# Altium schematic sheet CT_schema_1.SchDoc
size 645 x 603 mm
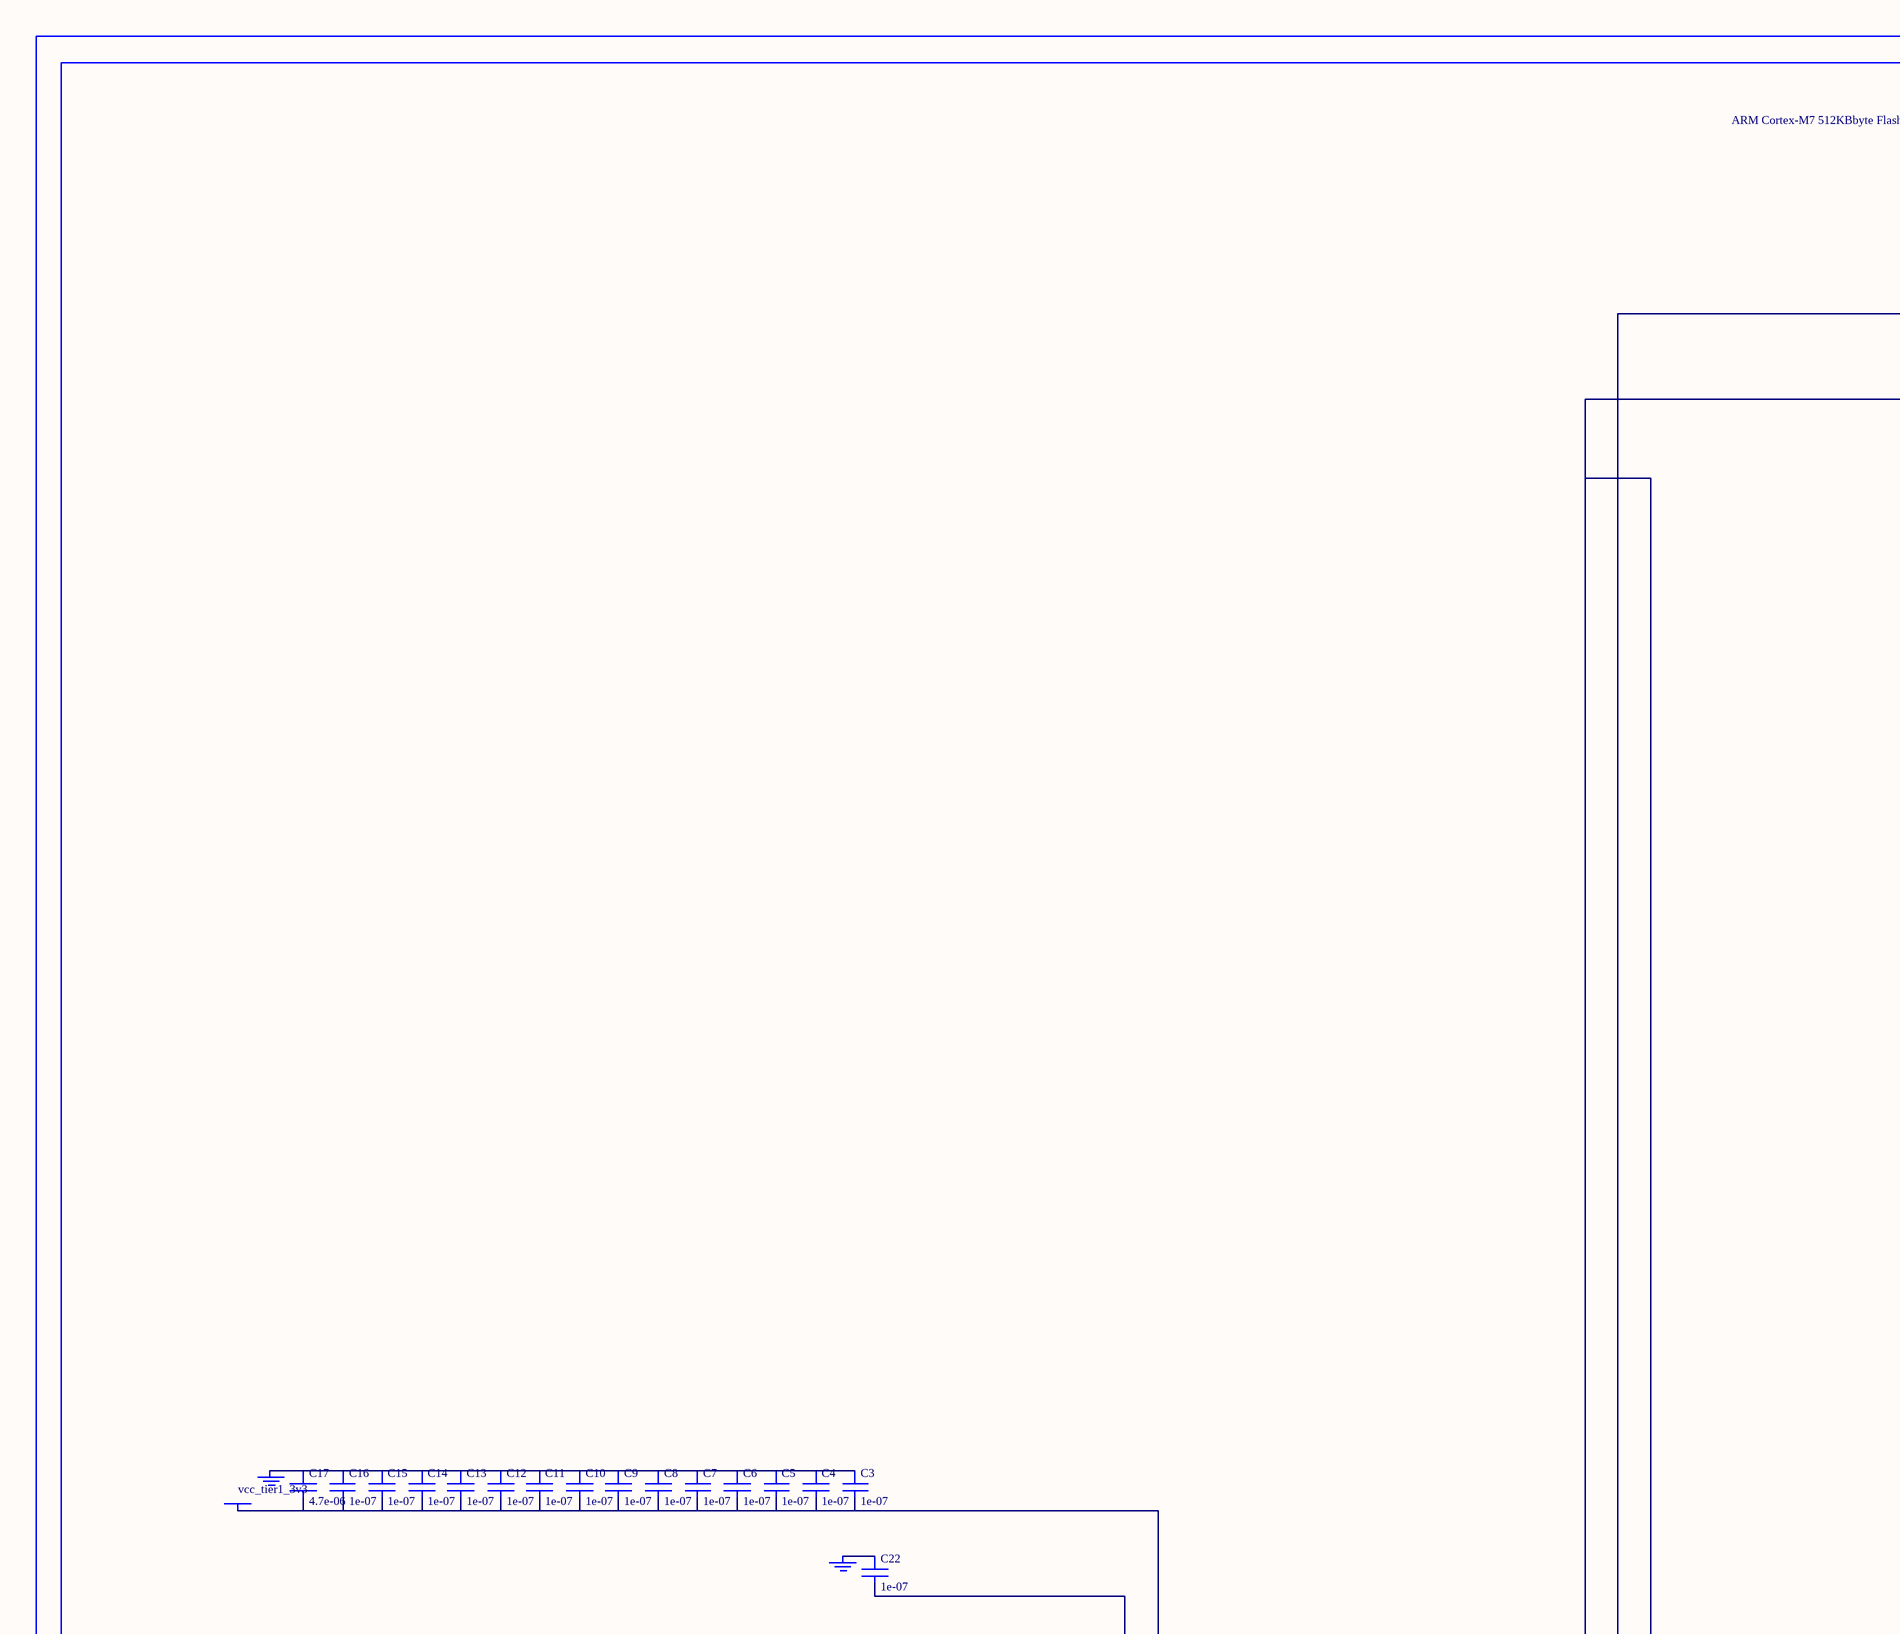
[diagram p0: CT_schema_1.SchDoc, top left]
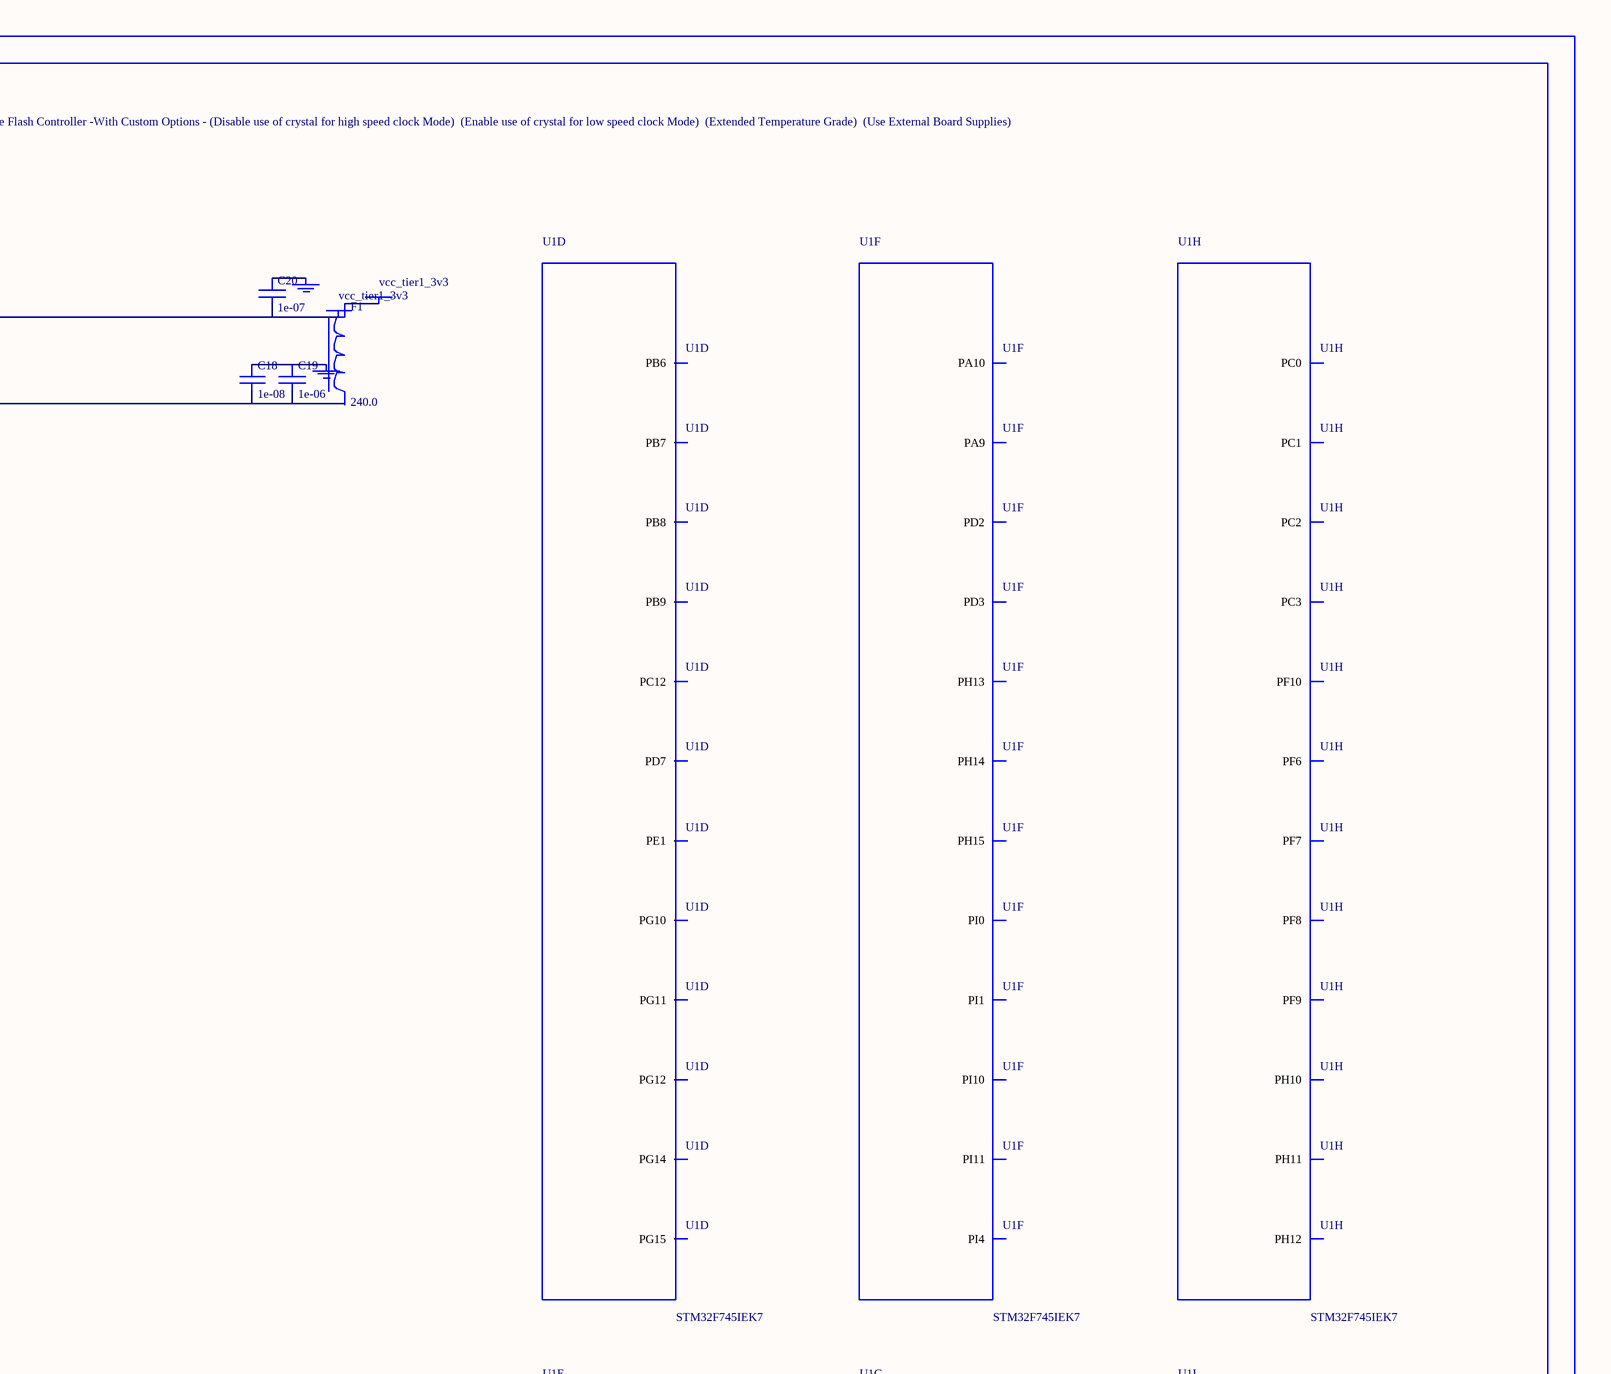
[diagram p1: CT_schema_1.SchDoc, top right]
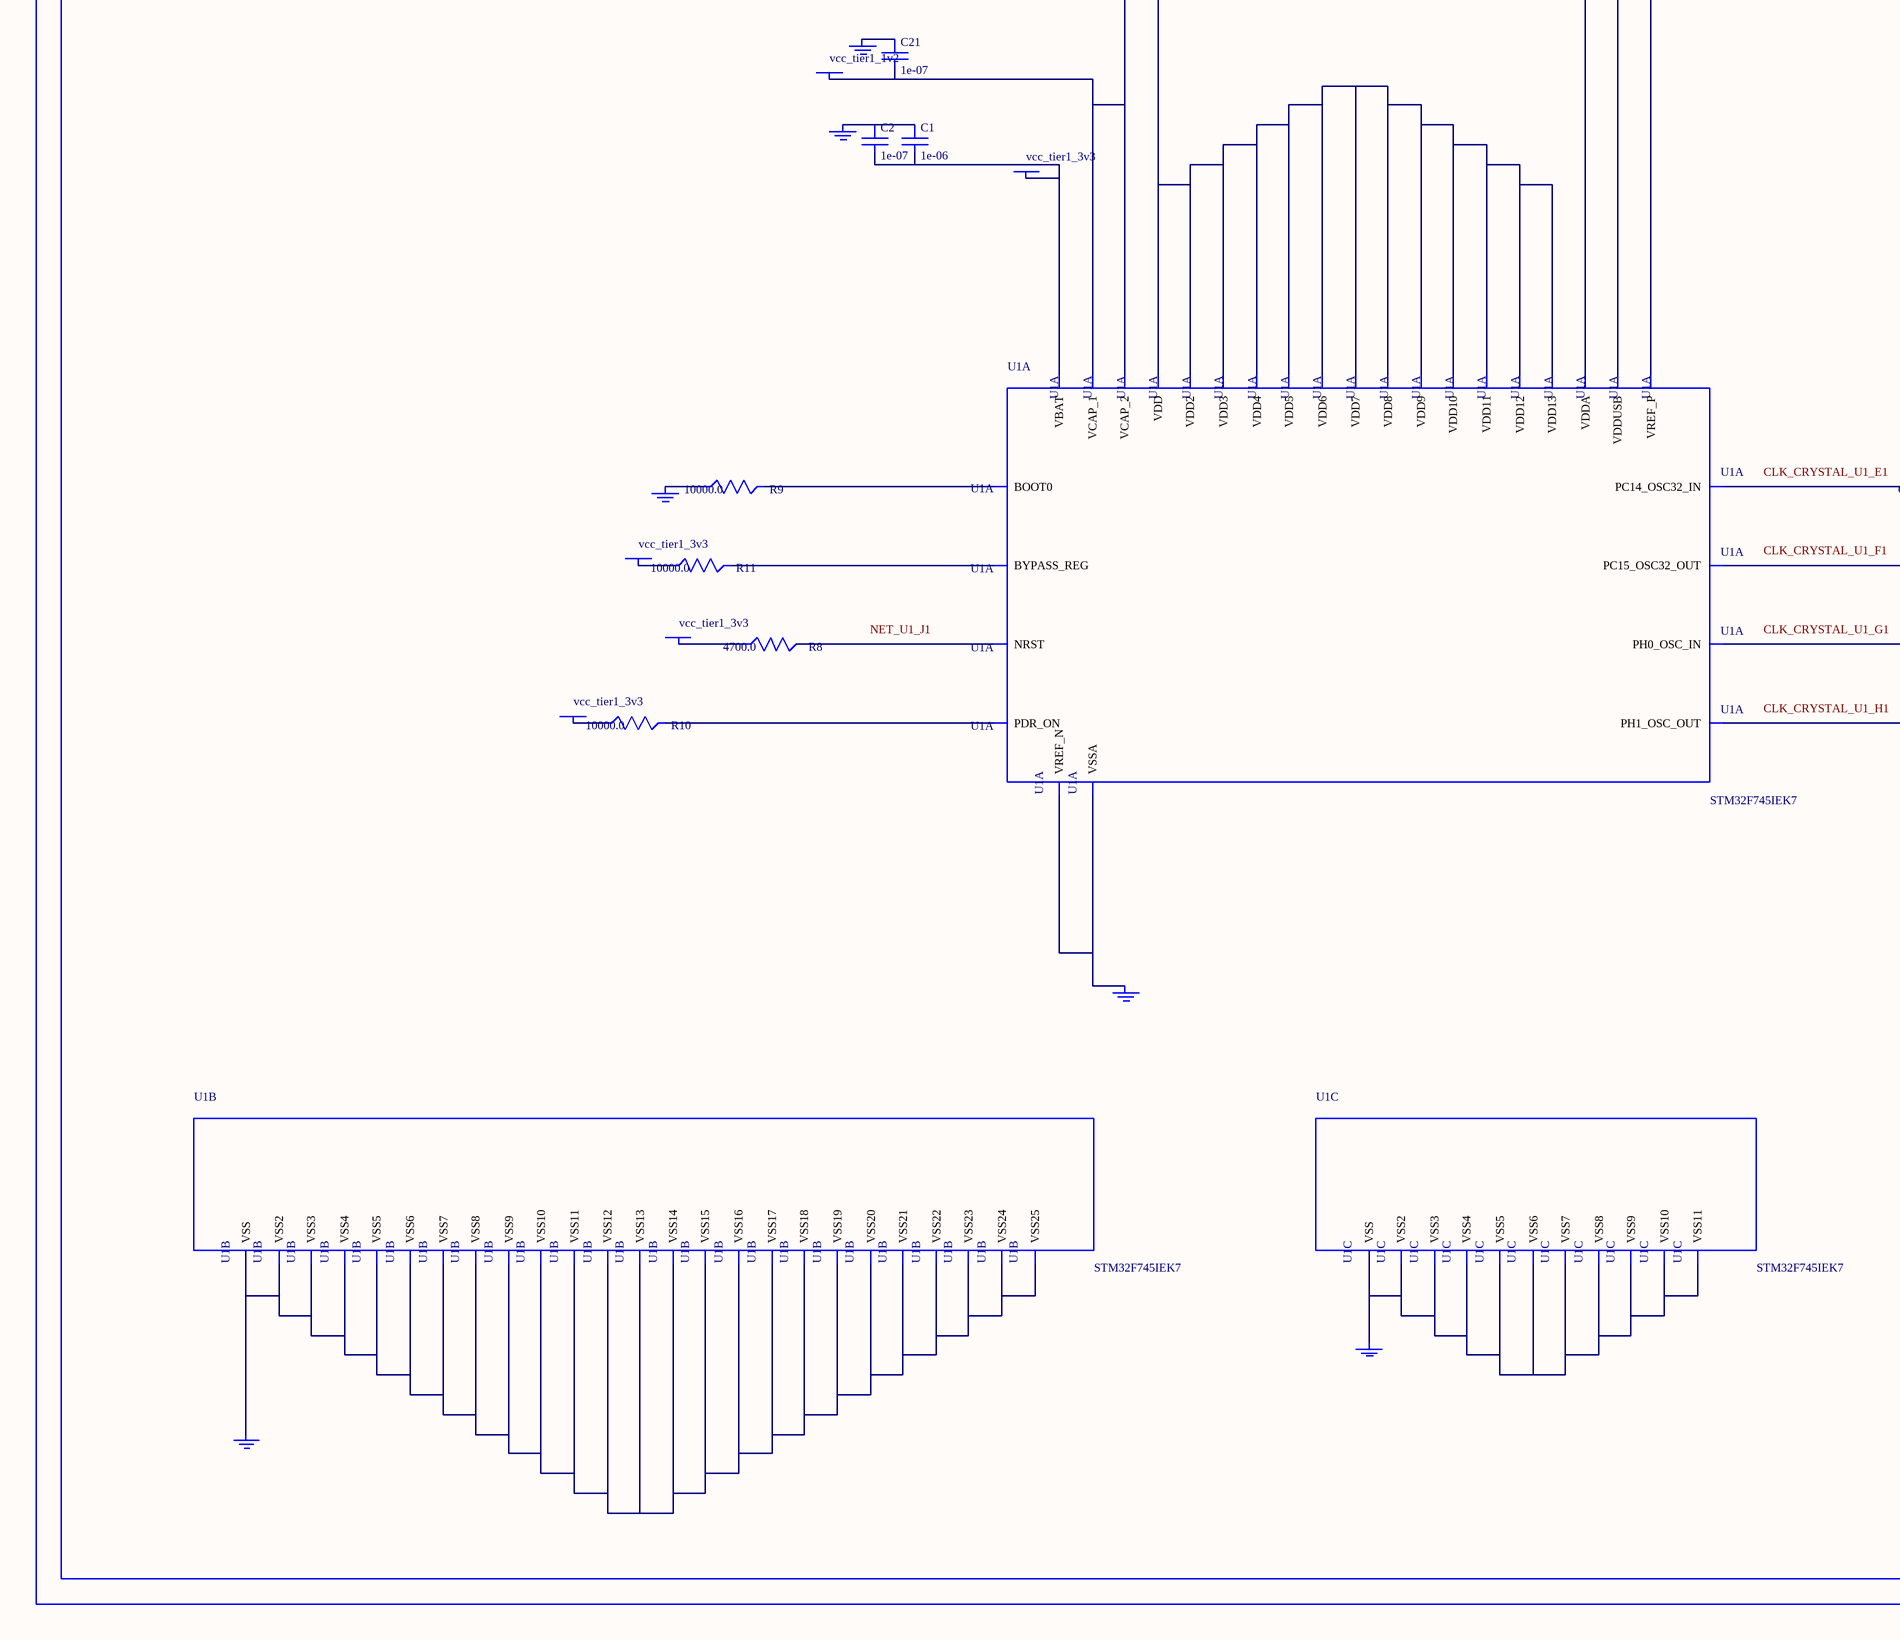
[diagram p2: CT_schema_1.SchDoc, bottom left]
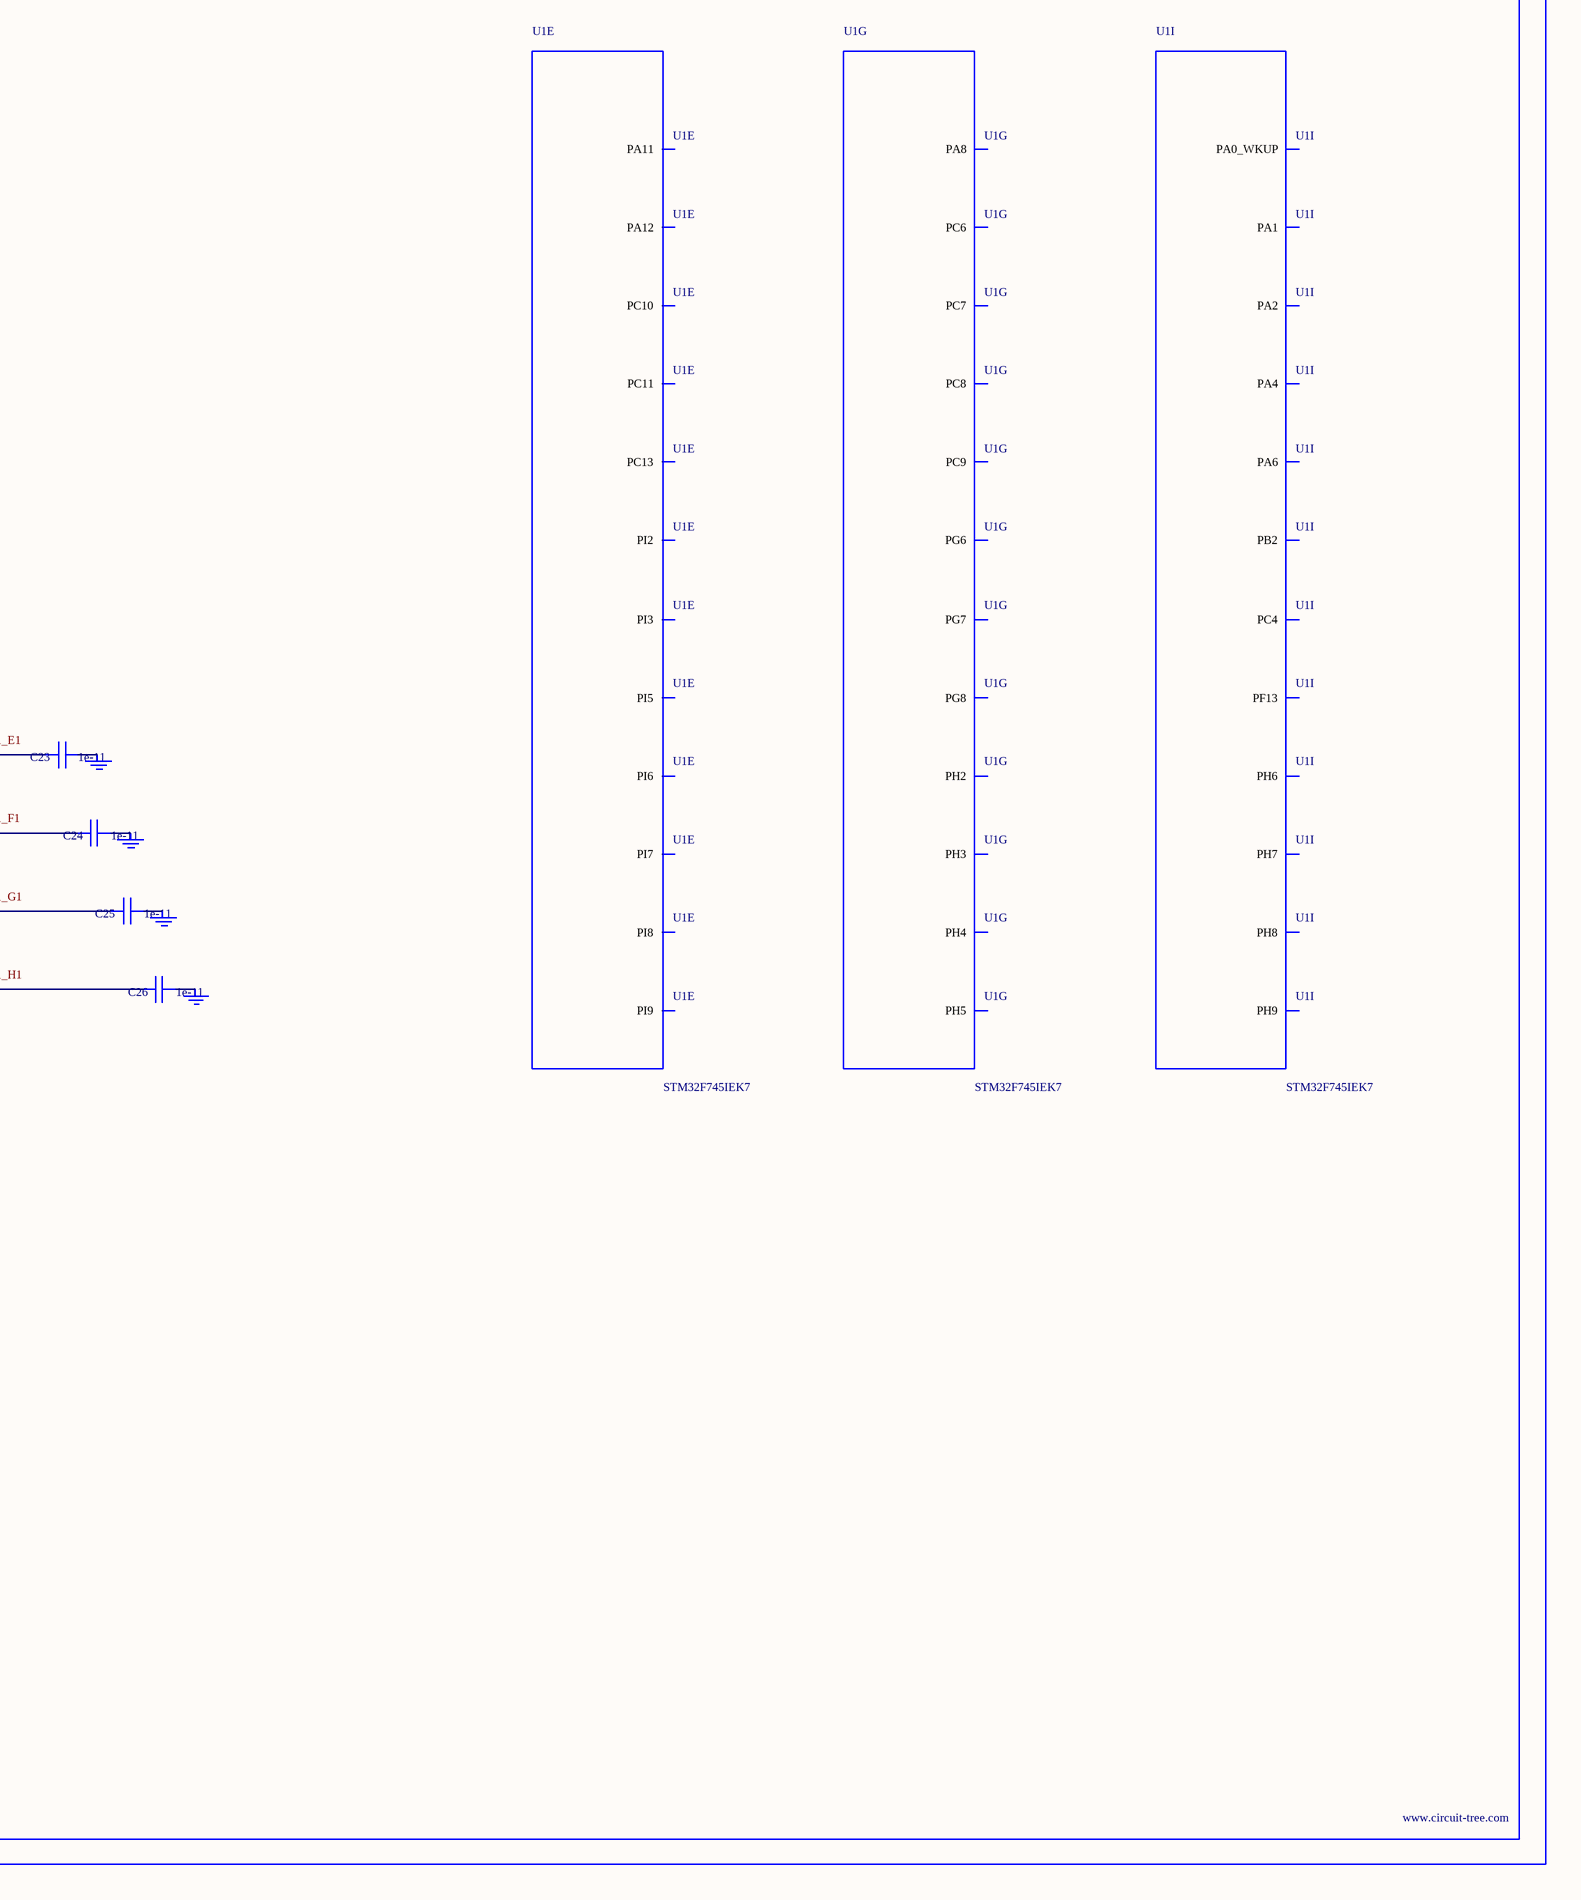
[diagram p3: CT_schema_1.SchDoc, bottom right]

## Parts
BORDER0  (no value)
C1  1e-06  [C0603]
C2  1e-07  [C0603]
C3  1e-07  [C0603]
C4  1e-07  [C0603]
C5  1e-07  [C0603]
C6  1e-07  [C0603]
C7  1e-07  [C0603]
C8  1e-07  [C0603]
C9  1e-07  [C0603]
C10  1e-07  [C0603]
C11  1e-07  [C0603]
C12  1e-07  [C0603]
C13  1e-07  [C0603]
C14  1e-07  [C0603]
C15  1e-07  [C0603]
C16  1e-07  [C0603]
C17  4.7e-06  [C0603]
C18  1e-08  [C0603]
C19  1e-06  [C0603]
C20  1e-07  [C0603]
C21  1e-07  [C0603]
C22  1e-07  [C0603]
C23  1e-11  [C0402]
C24  1e-11  [C0402]
C25  1e-11  [C0402]
C26  1e-11  [C0402]
F1  240.0  [L0603]
GND_INSTANCE_0_0  (no value)
GND_INSTANCE_0_1  (no value)
GND_INSTANCE_0_2  (no value)
GND_INSTANCE_0_3  (no value)
GND_INSTANCE_0_4  (no value)
GND_INSTANCE_0_5  (no value)
GND_INSTANCE_0_6  (no value)
GND_INSTANCE_0_7  (no value)
GND_INSTANCE_0_8  (no value)
GND_INSTANCE_0_9  (no value)
GND_INSTANCE_0_10  (no value)
GND_INSTANCE_0_11  (no value)
GND_INSTANCE_0_12  (no value)
GND_INSTANCE_0_13  (no value)
POWER_INSTANCE_0_0  vcc_tier1_3v3
POWER_INSTANCE_0_1  vcc_tier1_3v3
POWER_INSTANCE_0_2  vcc_tier1_3v3
POWER_INSTANCE_0_3  vcc_tier1_3v3
POWER_INSTANCE_0_4  vcc_tier1_3v3
POWER_INSTANCE_0_5  vcc_tier1_3v3
POWER_INSTANCE_0_6  vcc_tier1_1v2
POWER_INSTANCE_0_7  vcc_tier1_3v3
R8  4700.0  [R0603]
R9  10000.0  [R0603]
R10  10000.0  [R0603]
R11  10000.0  [R0603]
U1  STM32F745IEK7  [UFBGA176_25]  (parts A,B,C,D,E,F,G,H,I of 14)

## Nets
NetC1_1: C1.1 C2.1 GND_INSTANCE_0_0.0(GND)
NetC1_2: C1.2 C2.2 POWER_INSTANCE_0_0.0(PWR) U1.C1(VBAT)
NetC3_1: C3.1 C4.1 C5.1 C6.1 C7.1 C8.1 C9.1 C10.1 C11.1 C12.1 C13.1 C14.1 C15.1 C16.1 C17.1 GND_INSTANCE_0_2.0(GND)
NetC3_2: C3.2 C4.2 C5.2 C6.2 C7.2 C8.2 C9.2 C10.2 C11.2 C12.2 C13.2 C14.2 C15.2 C16.2 C17.2 POWER_INSTANCE_0_2.0(PWR) U1.C5(VDD) U1.C7(VDD2) U1.C8(VDD3) U1.C9(VDD4) U1.F3(VDD5) U1.G3(VDD7) U1.G13(VDD6) U1.J12(VDD8) U1.J13(VDD9) U1.K4(VDD10) U1.N8(VDD12) U1.N9(VDD13) U1.N10(VDD11)
NetC18_1: C18.1 C19.1 GND_INSTANCE_0_1.0(GND)
NetC18_2: C18.2 C19.2 U1.P1(VREF_P) U1.R1(VDDA)
NetC20_1: C20.1 GND_INSTANCE_0_4.0(GND)
NetC20_2: C20.2 POWER_INSTANCE_0_4.0(PWR) U1.H13(VDDUSB)
NetC21_1: C21.1 GND_INSTANCE_0_5.0(GND)
NetC21_2: C21.2 C22.2 POWER_INSTANCE_0_6.0(PWR) U1.F13(VCAP_2) U1.M10(VCAP_1)
NetC22_1: C22.1 GND_INSTANCE_0_6.0(GND)
NetC23_1: C23.1 GND_INSTANCE_0_7.0(GND)
NetC23_2: C23.2 U1.E1(PC14_OSC32_IN)
NetC24_1: C24.1 GND_INSTANCE_0_8.0(GND)
NetC24_2: C24.2 U1.F1(PC15_OSC32_OUT)
NetC25_1: C25.1 GND_INSTANCE_0_9.0(GND)
NetC25_2: C25.2 U1.G1(PH0_OSC_IN)
NetC26_1: C26.1 GND_INSTANCE_0_10.0(GND)
NetC26_2: C26.2 U1.H1(PH1_OSC_OUT)
NetF1_1: F1.1 POWER_INSTANCE_0_1.0(PWR)
NetGND_INSTANCE_0_3_0: GND_INSTANCE_0_3.0(GND) R9.1
NetGND_INSTANCE_0_11_0: GND_INSTANCE_0_11.0(GND) U1.M1(VSSA) U1.N1(VREF_N)
NetGND_INSTANCE_0_12_0: GND_INSTANCE_0_12.0(GND) U1.D5(VSS) U1.D7(VSS2) U1.D8(VSS3) U1.D9(VSS4) U1.F2(VSS7) U1.F6(VSS8) U1.F7(VSS9) U1.F8(VSS10) U1.F9(VSS11) U1.F10(VSS5) U1.F12(VSS6) U1.G2(VSS14) U1.G6(VSS15) U1.G7(VSS16) U1.G8(VSS17) U1.G9(VSS18) U1.G10(VSS12) U1.G12(VSS13) U1.H6(VSS21) U1.H7(VSS22) U1.H8(VSS23) U1.H9(VSS24) U1.H10(VSS19) U1.H12(VSS20) U1.J10(VSS25)
NetGND_INSTANCE_0_13_0: GND_INSTANCE_0_13.0(GND) U1.J6(VSS) U1.J7(VSS2) U1.J8(VSS3) U1.J9(VSS4) U1.K6(VSS6) U1.K7(VSS7) U1.K8(VSS8) U1.K9(VSS9) U1.K10(VSS5) U1.M8(VSS10) U1.M9(VSS11)
NetPOWER_INSTANCE_0_3_0: POWER_INSTANCE_0_3.0(PWR) R10.1
NetPOWER_INSTANCE_0_5_0: POWER_INSTANCE_0_5.0(PWR) R11.1
NetPOWER_INSTANCE_0_7_0: POWER_INSTANCE_0_7.0(PWR) R8.1
NetR8_2: R8.2 U1.J1(NRST)
NetR9_2: R9.2 U1.D6(BOOT0)
NetR10_2: R10.2 U1.C6(PDR_ON)
NetR11_2: R11.2 U1.L4(BYPASS_REG)

Not connected (* = marked no-connect by the designer): F1 2; U1 A3(PE1) A5(PB8) A7(PG14) A11(PD7) A12(PC12) B4(PB9) B5(PB7) B6(PB6) B7(PG15) B8(PG12) B9(PG11) B10(PG10) B13(PC11) B14(PC10) B15(PA12) C2(PI7) C3(PI6) C4(PI5) C13(PI3) C14(PI2) C15(PA11) D1(PC13) D2(PI8) D3(PI9) D4(PI4) D11(PD3) D12(PD2) D13(PH15) D14(PI1) D15(PA10) E3(PI10) E4(PI11) E12(PH13) E13(PH14) E14(PI0) E15(PA9) F4(PH2) F14(PC9) F15(PA8) G4(PH3) G14(PC8) G15(PC7) H4(PH4) H14(PG8) H15(PC6) J4(PH5) J14(PG7) J15(PG6) K1(PF7) K2(PF6) K12(PH12) L1(PF10) L2(PF9) L3(PF8) L12(PH11) L13(PH10) M2(PC0) M3(PC1) M4(PC2) M5(PC3) M6(PB2) M11(PH6) M12(PH8) M13(PH9) N2(PA1) N3(PA0_WKUP) N4(PA4) N5(PC4) N6(PF13) N12(PH7) P2(PA2) P3(PA6)

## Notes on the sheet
- Labels drawn without touching a wire or pin: CLK_CRYSTAL_U1_E1, CLK_CRYSTAL_U1_F1, CLK_CRYSTAL_U1_G1, CLK_CRYSTAL_U1_H1, NET_U1_J1

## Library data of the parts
BORDER0 = BORDER_PAGE0
C1 C19 = C0603C105K3RACTU
C2-C16 C20-C22 = 06035C104K4Z2A
C17 = GRM188R6YA475KE15D
C18 = 06035C103K4Z2A
C23-C26 = C0402C100K3GACTU
F1 = Z0603C241ASMST
GND_INSTANCE_0_0-GND_INSTANCE_0_13 = GND
POWER_INSTANCE_0_0-POWER_INSTANCE_0_7 = PWR
R8 = RC0603JR-074K7L
R9-R11 = RC0603JR-0710KL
